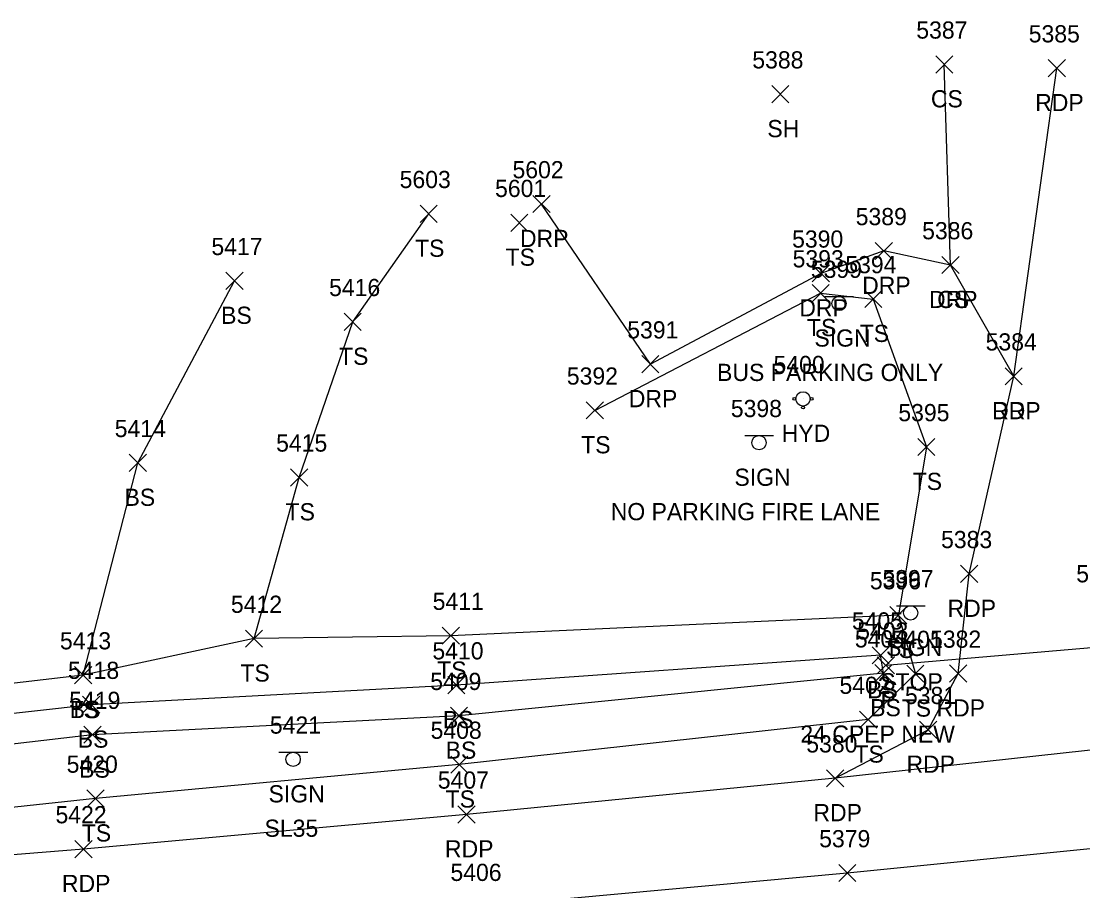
# Model space of a CAD drawing. Extents: x 1443912 to 1445411, y 621446 to 623693.
# Drawn here: x 1444289.1 to 1444412.6, y 622531.9 to 622633.1 of the extents above; entities that cross this region are included whole.
import ezdxf

# ---------------------------------------------------------------- set-up
doc = ezdxf.new("R2010")
doc.units = 0
for name, color, linetype in [('D_A', 7, 'Continuous'), ('D_C', 7, 'Continuous'), ('D_I', 7, 'Continuous'), ('D_TIC', 7, 'Continuous'), ('DCP', 7, 'Continuous'), ('L_A', 7, 'Continuous'), ('L_I', 7, 'Continuous'), ('L_TIC', 7, 'Continuous'), ('LELB', 7, 'Continuous'), ('P_A', 7, 'Continuous'), ('P_I', 7, 'Continuous'), ('P_TIC', 7, 'Continuous'), ('PET', 7, 'Continuous'), ('PRC', 7, 'Continuous'), ('R_A', 7, 'Continuous'), ('R_I', 7, 'Continuous'), ('R_TIC', 7, 'Continuous'), ('RDP', 7, 'Continuous'), ('S_A', 7, 'Continuous'), ('S_C', 7, 'Continuous'), ('S_I', 7, 'Continuous'), ('SSGN', 7, 'Continuous'), ('U_A', 7, 'Continuous'), ('U_I', 7, 'Continuous'), ('UWFH', 7, 'Continuous')]:
    doc.layers.add(name, color=color, linetype=linetype)

msp = doc.modelspace()

# ---------------------------------------------------------------- linework, layer by layer
at = {"layer": 'D_TIC'}
for points in [[(1444388.68, 622557.12), (1444390.68, 622559.12)], [(1444390.68, 622557.12), (1444388.68, 622559.12)]]:
    msp.add_lwpolyline(points, dxfattribs=at)
at = {"layer": 'DCP'}
msp.add_lwpolyline([(1444438.42, 622562.31), (1444389.68, 622558.12)], dxfattribs=at)
at = {"layer": 'L_TIC'}
for points in [[(1444395.48, 622627.05), (1444397.48, 622629.05)], [(1444397.48, 622627.05), (1444395.48, 622629.05)], [(1444376.4, 622623.58), (1444378.4, 622625.58)], [(1444378.4, 622623.58), (1444376.4, 622625.58)], [(1444335.49, 622609.66), (1444337.49, 622611.66)], [(1444337.49, 622609.66), (1444335.49, 622611.66)], [(1444346.03, 622608.62), (1444348.03, 622610.62)], [(1444348.03, 622608.62), (1444346.03, 622610.62)], [(1444396.21, 622603.7), (1444398.21, 622605.7)], [(1444398.21, 622603.7), (1444396.21, 622605.7)], [(1444312.9, 622601.86), (1444314.9, 622603.86)], [(1444314.9, 622601.86), (1444312.9, 622603.86)], [(1444381.09, 622600.43), (1444383.09, 622602.43)], [(1444383.09, 622600.43), (1444381.09, 622602.43)], [(1444387.22, 622599.75), (1444389.22, 622601.75)], [(1444389.22, 622599.75), (1444387.22, 622601.75)], [(1444326.65, 622597.09), (1444328.65, 622599.09)], [(1444328.65, 622597.09), (1444326.65, 622599.09)], [(1444354.82, 622586.79), (1444356.82, 622588.79)], [(1444356.82, 622586.79), (1444354.82, 622588.79)], [(1444354.82, 622586.79), (1444356.82, 622588.79)], [(1444356.82, 622586.79), (1444354.82, 622588.79)], [(1444393.39, 622582.53), (1444395.39, 622584.53)], [(1444395.39, 622582.53), (1444393.39, 622584.53)], [(1444301.66, 622580.68), (1444303.66, 622582.68)], [(1444303.66, 622580.68), (1444301.66, 622582.68)], [(1444320.43, 622578.99), (1444322.43, 622580.99)], [(1444322.43, 622578.99), (1444320.43, 622580.99)], [(1444390.13, 622562.97), (1444392.13, 622564.97)], [(1444392.13, 622562.97), (1444390.13, 622564.97)], [(1444390.13, 622562.97), (1444392.13, 622564.97)], [(1444392.13, 622562.97), (1444390.13, 622564.97)], [(1444315.17, 622560.23), (1444317.17, 622562.23)], [(1444317.17, 622560.23), (1444315.17, 622562.23)], [(1444315.17, 622560.23), (1444317.17, 622562.23)], [(1444317.17, 622560.23), (1444315.17, 622562.23)], [(1444338.07, 622560.57), (1444340.07, 622562.57)], [(1444340.07, 622560.57), (1444338.07, 622562.57)], [(1444388.07, 622558.29), (1444390.07, 622560.29)], [(1444390.07, 622558.29), (1444388.07, 622560.29)], [(1444295.28, 622555.98), (1444297.28, 622557.98)], [(1444297.28, 622555.98), (1444295.28, 622557.98)], [(1444295.28, 622555.98), (1444297.28, 622557.98)], [(1444297.28, 622555.98), (1444295.28, 622557.98)], [(1444388.41, 622556.2), (1444390.41, 622558.2)], [(1444390.41, 622556.2), (1444388.41, 622558.2)], [(1444388.41, 622556.2), (1444390.41, 622558.2)], [(1444390.41, 622556.2), (1444388.41, 622558.2)], [(1444392.11, 622556.15), (1444394.11, 622558.15)], [(1444394.11, 622556.15), (1444392.11, 622558.15)], [(1444338.7, 622554.81), (1444340.7, 622556.81)], [(1444340.7, 622554.81), (1444338.7, 622556.81)], [(1444296.22, 622552.54), (1444298.22, 622554.54)], [(1444298.22, 622552.54), (1444296.22, 622554.54)], [(1444339.01, 622551.25), (1444341.01, 622553.25)], [(1444341.01, 622551.25), (1444339.01, 622553.25)], [(1444386.61, 622550.8), (1444388.61, 622552.8)], [(1444388.61, 622550.8), (1444386.61, 622552.8)], [(1444296.37, 622549.05), (1444298.37, 622551.05)], [(1444298.37, 622549.05), (1444296.37, 622551.05)], [(1444339.05, 622545.57), (1444341.05, 622547.57)], [(1444341.05, 622545.57), (1444339.05, 622547.57)], [(1444296.72, 622541.62), (1444298.72, 622543.62)], [(1444298.72, 622541.62), (1444296.72, 622543.62)]]:
    msp.add_lwpolyline(points, dxfattribs=at)
at = {"layer": 'LELB'}
for points in [[(1444397.21, 622604.7), (1444396.48, 622628.05)], [(1444316.17, 622561.23), (1444321.43, 622579.99), (1444327.65, 622598.09), (1444336.49, 622610.66)], [(1444296.28, 622556.98), (1444302.66, 622581.68), (1444313.9, 622602.86)], [(1444355.82, 622587.79), (1444382.09, 622601.43), (1444388.22, 622600.75), (1444394.39, 622583.53), (1444391.13, 622563.97), (1444339.07, 622561.57), (1444316.17, 622561.23), (1444296.28, 622556.98), (1444246.36, 622551.15), (1444206.26, 622547.16), (1444161.92, 622543.9), (1444107.71, 622538.27), (1444059.83, 622532.81), (1444011.32, 622528.61), (1443962.45, 622523.89), (1443917.35, 622519.88)], [(1444391.13, 622563.97), (1444393.11, 622557.15), (1444387.61, 622551.8), (1444340.05, 622546.57), (1444297.72, 622542.62), (1444246.78, 622537.17), (1444208.05, 622534.52), (1444162.95, 622529.01), (1444109.78, 622525.06), (1444061.22, 622520.84), (1444012.05, 622517.25), (1443964.19, 622512.75), (1443917.37, 622507.84)], [(1444389.41, 622557.2), (1444389.07, 622559.29), (1444339.7, 622555.81), (1444297.22, 622553.54), (1444246.54, 622547.88), (1444206.48, 622544.61), (1444161.88, 622540.06), (1444108.12, 622535.29), (1444059.83, 622530.34), (1444011.69, 622526.21), (1443965.09, 622519.3), (1443918.03, 622516.72)], [(1444389.41, 622557.2), (1444340.01, 622552.25), (1444297.37, 622550.05), (1444246.69, 622544.15), (1444206.7, 622540.73), (1444161.88, 622535.5), (1444108.33, 622532.02), (1444060.68, 622526.05), (1444011.71, 622522.18), (1443963.48, 622517.56), (1443917.38, 622512.98)]]:
    msp.add_lwpolyline(points, dxfattribs=at)
at = {"layer": 'P_TIC'}
for points in [[(1444408.56, 622626.61), (1444410.56, 622628.61)], [(1444410.56, 622626.61), (1444408.56, 622628.61)], [(1444403.55, 622590.76), (1444405.55, 622592.76)], [(1444405.55, 622590.76), (1444403.55, 622592.76)], [(1444398.36, 622567.76), (1444400.36, 622569.76)], [(1444400.36, 622567.76), (1444398.36, 622569.76)], [(1444397.08, 622556.17), (1444399.08, 622558.17)], [(1444399.08, 622556.17), (1444397.08, 622558.17)], [(1444393.6, 622549.62), (1444395.6, 622551.62)], [(1444395.6, 622549.62), (1444393.6, 622551.62)], [(1444382.77, 622543.98), (1444384.77, 622545.98)], [(1444384.77, 622543.98), (1444382.77, 622545.98)], [(1444382.77, 622543.98), (1444384.77, 622545.98)], [(1444384.77, 622543.98), (1444382.77, 622545.98)], [(1444339.89, 622539.77), (1444341.89, 622541.77)], [(1444341.89, 622539.77), (1444339.89, 622541.77)], [(1444295.33, 622535.74), (1444297.33, 622537.74)], [(1444297.33, 622535.74), (1444295.33, 622537.74)], [(1444384.19, 622532.95), (1444386.19, 622534.95)], [(1444386.19, 622532.95), (1444384.19, 622534.95)]]:
    msp.add_lwpolyline(points, dxfattribs=at)
at = {"layer": 'PET'}
for points in [[(1444383.77, 622544.98), (1444394.6, 622550.62), (1444398.08, 622557.17), (1444399.36, 622568.76), (1444404.55, 622591.76), (1444409.56, 622627.61)], [(1444727.75, 622590.13), (1444719.16, 622580.43), (1444710.14, 622575.73), (1444699.63, 622573.2), (1444681.85, 622571.77), (1444667.76, 622571.14), (1444650.5, 622569.81), (1444612.69, 622566.37), (1444582.45, 622563.73), (1444564.11, 622562), (1444525.39, 622558.42), (1444488.31, 622554.6), (1444447.09, 622551.06), (1444415.95, 622548.51), (1444383.77, 622544.98), (1444340.89, 622540.77), (1444296.33, 622536.74), (1444247.14, 622532.77)]]:
    msp.add_lwpolyline(points, dxfattribs=at)
at = {"layer": 'PRC'}
msp.add_lwpolyline([(1444719.77, 622561.99), (1444681.72, 622559.72), (1444650.83, 622557.58), (1444613.8, 622554.84), (1444583.05, 622552.28), (1444545.98, 622548.57), (1444490.19, 622543.66), (1444448.69, 622540.02), (1444415.77, 622536.99), (1444385.19, 622533.95), (1444342.42, 622530.03), (1444296.8, 622526.08), (1444247.95, 622521.6), (1444210.22, 622518.45), (1444165.33, 622514.18), (1444110.47, 622509.68), (1444063.9, 622505.59), (1444012.84, 622501.59), (1443966.33, 622497.17), (1443919.63, 622492.61)], dxfattribs=at)
at = {"layer": 'R_TIC'}
for points in [[(1444348.62, 622610.8), (1444350.62, 622612.8)], [(1444350.62, 622610.8), (1444348.62, 622612.8)], [(1444388.44, 622605.34), (1444390.44, 622607.34)], [(1444390.44, 622605.34), (1444388.44, 622607.34)], [(1444396.21, 622603.7), (1444398.21, 622605.7)], [(1444398.21, 622603.7), (1444396.21, 622605.7)], [(1444381.12, 622602.73), (1444383.12, 622604.73)], [(1444383.12, 622602.73), (1444381.12, 622604.73)], [(1444361.28, 622592.16), (1444363.28, 622594.16)], [(1444363.28, 622592.16), (1444361.28, 622594.16)], [(1444403.55, 622590.76), (1444405.55, 622592.76)], [(1444405.55, 622590.76), (1444403.55, 622592.76)]]:
    msp.add_lwpolyline(points, dxfattribs=at)
at = {"layer": 'RDP'}
msp.add_lwpolyline([(1444404.55, 622591.76), (1444397.21, 622604.7), (1444389.44, 622606.34), (1444382.12, 622603.73), (1444362.28, 622593.16), (1444349.62, 622611.8)], dxfattribs=at)
at = {"layer": 'SSGN'}
for p, q in [((1444382.59, 622601.06), (1444385.92, 622601.06)), ((1444384.23, 622600.23), (1444384.23, 622600.23)), ((1444373.27, 622584.86), (1444376.61, 622584.86)), ((1444374.92, 622584.03), (1444374.92, 622584.03)), ((1444390.91, 622565.06), (1444394.25, 622565.06)), ((1444392.56, 622564.23), (1444392.56, 622564.23)), ((1444319.07, 622548.02), (1444322.41, 622548.02)), ((1444320.72, 622547.19), (1444320.72, 622547.19))]:
    msp.add_line(p, q, dxfattribs=at)
for centre in [(1444384.23, 622600.23), (1444374.92, 622584.03), (1444392.56, 622564.23), (1444320.72, 622547.19)]:
    msp.add_circle(centre, 0.833, dxfattribs=at)
at = {"layer": 'UWFH'}
msp.add_line((1444380.04, 622589.13), (1444380.04, 622589.13), dxfattribs=at)
for centre, radius in [((1444379.04, 622589.13), 0.167), ((1444380.04, 622589.13), 0.833), ((1444381.04, 622589.13), 0.167), ((1444380.04, 622588.13), 0.167)]:
    msp.add_circle(centre, radius, dxfattribs=at)

# ---------------------------------------------------------------- texts
at = {"layer": 'D_A'}
msp.add_text('P', height=2, dxfattribs=at).set_placement((1444389.06, 622553.12))
at = {"layer": 'D_C'}
msp.add_text('24 CPEP NEW', height=2, dxfattribs=at).set_placement((1444379.73, 622549.12))
at = {"layer": 'D_I'}
msp.add_text('5403', height=2, dxfattribs=at).set_placement((1444386.34, 622561.12))
at = {"layer": 'L_A'}
for s, p in [('CS', (1444394.92, 622623.05)), ('SH', (1444375.89, 622619.58)), ('TS', (1444334.9, 622605.66)), ('TS', (1444345.44, 622604.62)), ('CS', (1444395.65, 622599.7)), ('BS', (1444312.34, 622597.86)), ('TS', (1444380.5, 622596.43)), ('TS', (1444386.63, 622595.75)), ('TS', (1444326.06, 622593.09)), ('TS', (1444354.23, 622582.79)), ('TS', (1444354.23, 622582.79)), ('TS', (1444392.8, 622578.53)), ('BS', (1444301.1, 622576.68)), ('TS', (1444319.84, 622574.99)), ('TS', (1444389.54, 622558.97)), ('TS', (1444389.54, 622558.97)), ('TS', (1444314.58, 622556.23)), ('TS', (1444314.58, 622556.23)), ('TS', (1444337.48, 622556.57)), ('BS', (1444387.51, 622554.29)), ('BS', (1444387.85, 622552.2)), ('BS', (1444387.85, 622552.2)), ('TS', (1444294.69, 622551.98)), ('BS', (1444294.72, 622551.98)), ('TS', (1444391.52, 622552.15)), ('BS', (1444338.14, 622550.81)), ('BS', (1444295.66, 622548.54)), ('BS', (1444338.46, 622547.25)), ('TS', (1444386.02, 622546.8)), ('BS', (1444295.82, 622545.05)), ('TS', (1444338.46, 622541.57)), ('TS', (1444296.13, 622537.62))]:
    msp.add_text(s, height=2, dxfattribs=at).set_placement(p)
at = {"layer": 'L_I'}
for s, p in [('5387', (1444393.22, 622631.05)), ('5388', (1444374.14, 622627.58)), ('5603', (1444333.11, 622613.66)), ('5601', (1444344.21, 622612.62)), ('5386', (1444393.9, 622607.7)), ('5417', (1444311.21, 622605.86)), ('5393', (1444378.83, 622604.43)), ('5394', (1444384.96, 622603.75)), ('5416', (1444324.9, 622601.09)), ('5392', (1444352.56, 622590.79)), ('5392', (1444352.56, 622590.79)), ('5395', (1444391.13, 622586.53)), ('5414', (1444299.96, 622584.68)), ('5415', (1444318.74, 622582.99)), ('5396', (1444387.82, 622566.97)), ('5396', (1444387.82, 622566.97)), ('5411', (1444336.95, 622564.57)), ('5412', (1444313.48, 622564.23)), ('5412', (1444313.48, 622564.23)), ('5405', (1444385.73, 622562.29)), ('5413', (1444293.59, 622559.98)), ('5413', (1444293.59, 622559.98)), ('5404', (1444386.07, 622560.2)), ('5404', (1444386.07, 622560.2)), ('5401', (1444390.34, 622560.15)), ('5410', (1444336.92, 622558.81)), ('5418', (1444294.53, 622556.54)), ('5409', (1444336.67, 622555.25)), ('5402', (1444384.28, 622554.8)), ('5419', (1444294.67, 622553.05)), ('5408', (1444336.71, 622549.57)), ('5420', (1444294.37, 622545.62))]:
    msp.add_text(s, height=2, dxfattribs=at).set_placement(p)
at = {"layer": 'P_A'}
for p in [(1444407.05, 622622.61), (1444402.04, 622586.76), (1444396.85, 622563.76), (1444395.57, 622552.17), (1444392.08, 622545.62), (1444381.25, 622539.98), (1444381.25, 622539.98), (1444338.38, 622535.77), (1444293.82, 622531.74)]:
    msp.add_text('RDP', height=2, dxfattribs=at).set_placement(p)
at = {"layer": 'P_I'}
for s, p in [('5385', (1444406.3, 622630.61)), ('5384', (1444401.29, 622594.76)), ('5383', (1444396.1, 622571.76)), ('5375', (1444411.83, 622567.78)), ('5382', (1444394.82, 622560.17)), ('5381', (1444391.9, 622553.62)), ('5380', (1444380.42, 622547.98)), ('5380', (1444380.42, 622547.98)), ('5407', (1444337.55, 622543.77)), ('5422', (1444293.07, 622539.74)), ('5379', (1444381.92, 622536.95)), ('5406', (1444339.02, 622533.03))]:
    msp.add_text(s, height=2, dxfattribs=at).set_placement(p)
at = {"layer": 'R_A'}
for p in [(1444347.11, 622606.8), (1444386.92, 622601.34), (1444394.7, 622599.7), (1444379.61, 622598.73), (1444359.77, 622588.16), (1444402.04, 622586.76)]:
    msp.add_text('DRP', height=2, dxfattribs=at).set_placement(p)
at = {"layer": 'R_I'}
for s, p in [('5602', (1444346.24, 622614.8)), ('5389', (1444386.17, 622609.34)), ('5390', (1444378.77, 622606.73)), ('5386', (1444393.9, 622607.7)), ('5391', (1444359.59, 622596.16)), ('5384', (1444401.29, 622594.76))]:
    msp.add_text(s, height=2, dxfattribs=at).set_placement(p)
at = {"layer": 'S_A'}
for p in [(1444381.37, 622595.21), (1444372.06, 622579.01), (1444389.7, 622559.21), (1444317.86, 622542.17)]:
    msp.add_text('SIGN', height=2, dxfattribs=at).set_placement(p)
at = {"layer": 'S_C'}
for s, p in [('BUS PARKING ONLY', (1444370.04, 622591.21)), ('NO PARKING FIRE LANE', (1444357.67, 622575.01)), ('STOP', (1444389.02, 622555.21)), ('SL35', (1444317.39, 622538.17))]:
    msp.add_text(s, height=2, dxfattribs=at).set_placement(p)
at = {"layer": 'S_I'}
for s, p in [('5399', (1444380.95, 622603.21)), ('5398', (1444371.64, 622587.01)), ('5397', (1444389.28, 622567.21)), ('5421', (1444318.01, 622550.17))]:
    msp.add_text(s, height=2, dxfattribs=at).set_placement(p)
at = {"layer": 'U_A'}
msp.add_text('HYD', height=2, dxfattribs=at).set_placement((1444377.56, 622584.13))
at = {"layer": 'U_I'}
msp.add_text('5400', height=2, dxfattribs=at).set_placement((1444376.61, 622592.13))

doc.saveas('drawing.dxf')
